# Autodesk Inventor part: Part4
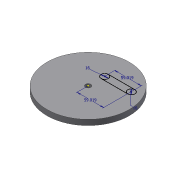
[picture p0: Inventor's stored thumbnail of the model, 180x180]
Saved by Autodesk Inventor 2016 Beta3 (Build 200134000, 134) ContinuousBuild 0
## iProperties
Created: 2016-03
Part Number: Part4
Material: Generic
Document SubType Name: Modeling
Designer: Gaurav
Density: 1 g/cm^3
Appearance: Default
Author: Gaurav
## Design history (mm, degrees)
sketch "Sketch1"
  geometry: C1 r 6 at (0, 0) reference; C2 r 6 at (0, 0); C3 r 91.109 at (0, 0); 1 further point
  constraints: 2 centre point, 2 coincident, 1 concentric
extrude "Extrusion1" new body sketch "Sketch1" distance "d0" = 12; taper "d1" = 0 deg
sketch "Sketch2"
  geometry: L1 (77.401, 9.763)-(1.535, 77.999); L2 (-9.763, 77.401)-(-77.999, 1.535); L3 (-77.401, -9.763)-(-1.535, -77.999); L4 (9.763, -77.401)-(77.999, -1.535); L5 (-3.217, 60.753)-(60.753, 3.217); L6 (60.753, 3.217)-(3.217, -60.753); L7 (3.217, -60.753)-(-60.753, -3.217); L8 (-60.753, -3.217)-(-3.217, 60.753); C1 r 6 at (0, 0) reference; A1 r 8 centre (72.019, -2) between (72.019, 6) and (72.019, -10) reference; A2 r 8 centre (-72.051, -3.815) between (-77.999, 1.535) and (-77.401, -9.763); A3 r 8 centre (3.815, -72.051) between (-1.535, -77.999) and (9.763, -77.401); A4 r 8 centre (72.051, 3.815) between (77.999, -1.535) and (77.401, 9.763); A5 r 8 centre (-3.815, 72.051) between (1.535, 77.999) and (-9.763, 77.401); 3 further points
  constraints: 16 end point, 8 point on circle, 8 tangent, 6 point on line, 4 centre point, 4 perpendicular, 3 equal radius, 1 parallel, 3 other
  dimensions: "d10" = 118.038 distance of point (-4.414, 83.349) point (-83.349, -4.414); "d11" = 118.038 distance of point (4.414, -83.349) point (-83.349, -4.414); "d12" = 8 radius of A2; "d13" = 16 distance between parallel lines of L1 L5
extrude "Extrusion2" cut sketch "Sketch2" distance "d14" = 5; taper "d15" = 0 deg
body "Solid1"
node "Reference1"
node "Reference2"
